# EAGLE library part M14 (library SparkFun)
Header 14 Standard 14-pin 0.1" header. Use with straight break away headers (SKU : PType-HD), right angle break away headers (PType-HD-RightAngle), swiss pins (PType-30F), machine pins (PType-MP), and female headers (PType-FH). Molex polarized connector foot print use with SKU : Con-Hdr with associated crimp pins and housings.
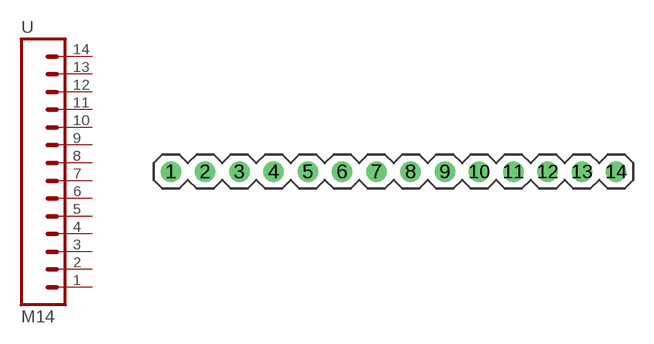
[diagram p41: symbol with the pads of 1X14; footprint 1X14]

Designator prefix -

## M14  [1X14]
1  1  pas
2  2  pas
3  3  pas
4  4  pas
5  5  pas
6  6  pas
7  7  pas
8  8  pas
9  9  pas
10  10  pas
11  11  pas
12  12  pas
13  13  pas
14  14  pas

## Footprint 1X14 (pad centres in mm)
drill 1.016 round: 1 0,0; 2 2.54,0; 3 5.08,0; 4 7.62,0; 5 10.16,0; 6 12.7,0; 7 15.24,0; 8 17.78,0; 9 20.32,0; 10 22.86,0; 11 25.4,0; 12 27.94,0; 13 30.48,0; 14 33.02,0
